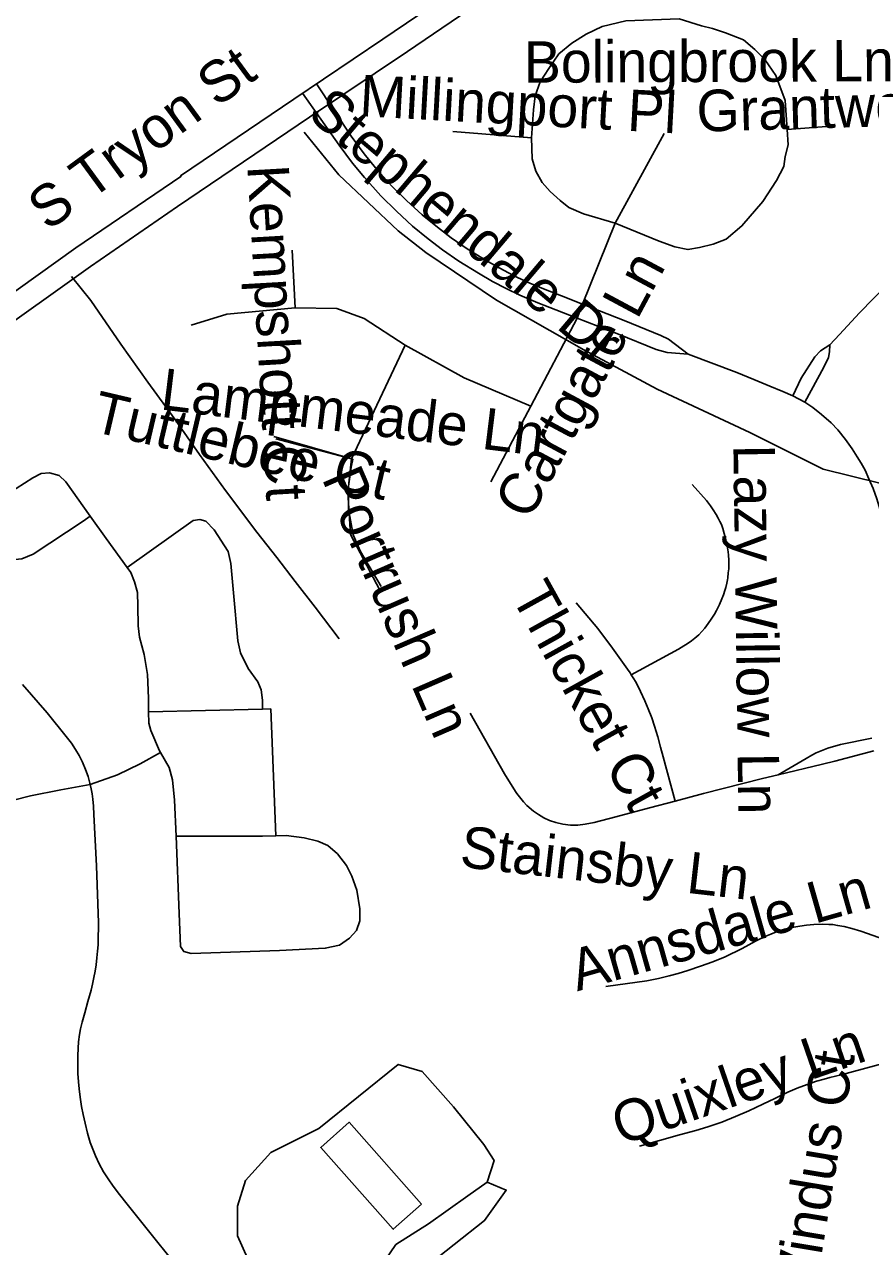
# Model space of a CAD drawing. Extents: x 1383679 to 1536984, y 460658 to 651027.
# Drawn here: x 1408734 to 1410672, y 498254 to 501053 of the extents above; entities that cross this region are included whole.
import ezdxf

# ---------------------------------------------------------------- set-up
doc = ezdxf.new("R2010")
doc.units = 0
for name, color, linetype in [('Exist Cultural Warehouse Building Footprint', 7, 'Continuous'), ('Exist Hydrographic Creek Single Shore', 7, 'Continuous'), ('Exist Road Non-System Type 51', 7, 'Continuous'), ('Exist Road Non-System Type 51 Label', 7, 'Continuous'), ('Exist Road Primary NC Label', 7, 'Continuous'), ('Exist Road Primary NC UnDivided 4 Lane Attributed', 7, 'Continuous')]:
    doc.layers.add(name, color=color, linetype=linetype)

msp = doc.modelspace()

# ---------------------------------------------------------------- linework, layer by layer
at = {"layer": 'Exist Cultural Warehouse Building Footprint'}
msp.add_lwpolyline([(1409643.3, 498351), (1409578.4, 498293.6), (1409412.5, 498481.2), (1409477.4, 498538.6), (1409643.3, 498351)], dxfattribs=at)
at = {"layer": 'Exist Hydrographic Creek Single Shore'}
msp.add_lwpolyline([(1409374.1, 500806), (1409454.2, 500708.4), (1409589.7, 500580.2), (1409652.9, 500530.4), (1409814.8, 500421.4), (1410014.7, 500307.3), (1410183, 500217.8), (1410395.1, 500118.3), (1410563.6, 500034.5), (1410693, 500002.4), (1410764.3, 499962.4), (1410867.4, 499916.8), (1411025, 499891.5), (1411092.9, 499884.4), (1411204.1, 499841.9), (1411305.7, 499821.8), (1411463.5, 499808.8), (1411647.5, 499803.5), (1411737.3, 499786.1), (1411800.7, 499760.2)], dxfattribs=at)
at = {"layer": 'Exist Road Non-System Type 51'}
for p, q in [((1409895.2, 500793.4), (1409715.2, 500807.8)), ((1410086.6, 500598), (1410198.9, 500803)), ((1410481.2, 500812.6), (1410591.7, 500820.6)), ((1410012.3, 500412), (1410086.6, 500598)), ((1409999.6, 500380.5), (1410012.3, 500412)), ((1410493.6, 500202), (1410521.4, 500187.8)), ((1409304.6, 500109.5), (1409486.1, 500057.5)), ((1409279, 499484.8), (1409018.2, 499478.7))]:
    msp.add_line(p, q, dxfattribs=at)
for points in [[(1410233.6, 501065.7), (1410111.4, 501060.9), (1410056.9, 501048), (1410020.6, 501030.4), (1409987.6, 501009.6), (1409957.9, 500985.6), (1409934.8, 500952), (1409915, 500921.5), (1409903.4, 500889.5), (1409900.1, 500857.5), (1409895.2, 500793.4)], [(1410481.2, 500812.6), (1410476.2, 500878.3), (1410454.7, 500935.9), (1410430, 500972.8), (1410406.9, 500995.2), (1410380.5, 501017.6), (1410339.2, 501033.6), (1410309.5, 501043.2), (1410284.7, 501049.6), (1410233.6, 501065.7)], [(1409403, 500917), (1409482.1, 500796.6), (1409512.2, 500756.4), (1409538.2, 500724.3), (1409574.7, 500683.6), (1409609.2, 500649.7), (1409644.9, 500616.9), (1409679.5, 500588.8), (1409711.2, 500564.3), (1409747.5, 500539.3), (1409791, 500512.2), (1409822.4, 500494.3), (1409852.1, 500478.6), (1409882.2, 500464.1), (1409922.5, 500447), (1409963.6, 500431.3), (1410012.3, 500412)], [(1409370.5, 500895.1), (1409454.7, 500776.5), (1409485.3, 500735.5), (1409512.3, 500702.2), (1409550.1, 500660.1), (1409585.8, 500625), (1409622.7, 500591.1), (1409658.4, 500562.2), (1409691.1, 500536.9), (1409728.8, 500510.8), (1409773.5, 500483), (1409806, 500464.5), (1409836.8, 500448.2), (1409868.1, 500433.1), (1409909.8, 500415.4), (1409951.3, 500399.6), (1409999.6, 500380.5)], [(1410086.6, 500598), (1410187.3, 500556.4), (1410223.6, 500543.6), (1410253.4, 500537.2), (1410279.8, 500542), (1410311.1, 500550), (1410340.8, 500561.2), (1410377.2, 500591.6), (1410425, 500647.7), (1410456.4, 500695.7), (1410472.9, 500727.7), (1410476.2, 500750.2), (1410482.8, 500777.4), (1410481.2, 500812.6)], [(1409895.2, 500793.4), (1409896.8, 500745.4), (1409905.1, 500716.5), (1409919.9, 500690.9), (1409938.1, 500670.1), (1409961.2, 500649.3), (1409981, 500633.3), (1410014, 500618.8), (1410086.6, 500598)], [(1409893.5, 500178.8), (1409741.3, 500243.5), (1409605.8, 500318.6), (1409511.9, 500379.1), (1409449.4, 500402), (1409353.5, 500404.1), (1409347.2, 500535.6)], [(1408841.6, 500475.6), (1408885.9, 500420.3), (1408954.3, 500320.5), (1409016.7, 500233.6), (1409077.9, 500148.8), (1409134.9, 500067.7), (1409194.5, 499985.4), (1409266.1, 499890.4), (1409312.1, 499831.8), (1409354.1, 499776.8), (1409399.8, 499718.4), (1409454.6, 499645.8)], [(1410578.3, 500318.8), (1410600.7, 500343.1), (1410646.3, 500392.6), (1410709.8, 500457.1), (1410733.4, 500481.8)], [(1410012.3, 500412), (1410107.1, 500374.8), (1410191.7, 500340.6), (1410208.8, 500332), (1410253.7, 500298)], [(1409353.5, 500404.1), (1409197.1, 500389.5), (1409115.8, 500364.5)], [(1409999.6, 500380.5), (1409893.5, 500178.8), (1409801.8, 500005.6)], [(1409999.6, 500380.5), (1410094.5, 500343.2), (1410181.1, 500308.2), (1410206.3, 500301.8), (1410253.7, 500298)], [(1409605.8, 500318.6), (1409482.7, 500057.8), (1409309.7, 500103.7)], [(1410253.7, 500298), (1410365.3, 500256), (1410404.5, 500239.9), (1410441.4, 500224.8), (1410470.6, 500212.4), (1410493.6, 500202)], [(1410493.6, 500202), (1410513.2, 500243.1), (1410544.1, 500291.3), (1410556.9, 500305.3), (1410578.3, 500318.8)], [(1410521.4, 500187.8), (1410564.8, 500268), (1410575.6, 500290.2), (1410577.5, 500302.7), (1410578.3, 500318.8)], [(1410521.4, 500187.8), (1410539.3, 500175.6), (1410559.8, 500159.5), (1410581.6, 500140.2), (1410596.7, 500124.3), (1410614.2, 500102.2), (1410629.5, 500081), (1410641.5, 500062.9), (1410650.3, 500048.4), (1410659.2, 500031.8), (1410668.2, 500012.2), (1410677.6, 499989.7), (1410686.3, 499966.7), (1410693.3, 499943.7), (1410697.5, 499926), (1410700.9, 499908.8), (1410703.3, 499890.7), (1410704.4, 499880.1), (1410705.7, 499857.8), (1410705.5, 499840.1), (1410704.4, 499814.2), (1410703, 499794.9)], [(1409482.7, 500057.8), (1409474.4, 499980.6), (1409480.7, 499884.6), (1409547.4, 499757.4)], [(1409486.1, 500057.5), (1409481.8, 500038.6), (1409476, 499995.2), (1409475.8, 499943), (1409486.9, 499884.2), (1409503.2, 499846.1), (1409551, 499765.3)], [(1408648.6, 499842.5), (1408654.9, 499863.9), (1408658.1, 499886), (1408653.9, 499915.6), (1408653.9, 499931.4), (1408662.2, 499949.3), (1408696, 499977.8), (1408753, 500014.7), (1408771.9, 500024.2), (1408790.9, 500026.2), (1408813.1, 500020), (1408828.9, 500005.2), (1408884.6, 499926.4)], [(1410123.7, 499563.7), (1410231.9, 499622.4), (1410243.9, 499629.4), (1410251.8, 499634.7), (1410261.4, 499641.4), (1410269, 499647.3), (1410278.2, 499655.2), (1410285.7, 499662.7), (1410292.2, 499669.9), (1410299.9, 499680.6), (1410306.9, 499690.7), (1410314.3, 499702.5), (1410318.7, 499710.6), (1410322.8, 499718.2), (1410325.7, 499724.3), (1410331.4, 499737.3), (1410334.8, 499746.4), (1410338.1, 499756.3), (1410340.3, 499763.1), (1410342.5, 499772.9), (1410344, 499781), (1410344.7, 499785.8), (1410346, 499797), (1410346.9, 499806.4), (1410347.3, 499813.6), (1410347.1, 499826.1), (1410346.4, 499837.2), (1410345.5, 499845.1), (1410344, 499854.1), (1410341.9, 499865), (1410340.5, 499872.2), (1410336.8, 499886.7), (1410333.3, 499898.5), (1410330.2, 499907.4), (1410326.8, 499914.6), (1410323, 499922.1), (1410318.2, 499930.6), (1410311.4, 499941.1), (1410304.9, 499950.5), (1410296.4, 499962.5), (1410263.3, 499999)], [(1408884.6, 499926.4), (1408867.9, 499915.6), (1408754, 499839.7), (1408727.6, 499829.1), (1408705.5, 499827), (1408668.6, 499836.5), (1408648.6, 499842.5)], [(1408884.6, 499926.4), (1408920.6, 499875.5), (1408969, 499809.2)], [(1408969, 499809.2), (1409119.9, 499916.6), (1409135.8, 499918.8), (1409149.5, 499915.6), (1409168.4, 499895.5), (1409200.1, 499846), (1409206.4, 499818.6), (1409212.8, 499751.1), (1409222.2, 499641.4), (1409228.6, 499614), (1409246.5, 499578.1), (1409268.6, 499547.5), (1409276, 499528.6), (1409279.1, 499505.3), (1409279, 499484.8)], [(1408969, 499809.2), (1408977.6, 499797.5), (1408986, 499776.3), (1408992.4, 499752.1), (1408993.4, 499720.5), (1408994.4, 499675.2), (1408997.6, 499649.8), (1409008.1, 499609.8), (1409015.5, 499564.4), (1409017.6, 499509.6), (1409018.2, 499478.7)], [(1409997.5, 499728.4), (1410047.5, 499669.4), (1410081.1, 499624.5), (1410115.4, 499576.6), (1410121, 499568), (1410123.7, 499563.7)], [(1408729.1, 499541.4), (1408785.4, 499476), (1408829.6, 499421.9), (1408841.4, 499406.5), (1408850.8, 499392.6), (1408858.9, 499378.6), (1408866.7, 499363.1), (1408873.7, 499346.2), (1408879.4, 499330.3), (1408883.8, 499315.2), (1408886.8, 499301.9), (1408888.8, 499290.7), (1408890.3, 499278.9), (1408892.1, 499262.3), (1408892.9, 499243.5), (1408898.8, 499125.8), (1408903.2, 498995.6), (1408903.4, 498981.7), (1408902.8, 498965.8), (1408902.3, 498944.8), (1408901.3, 498930.5), (1408899.9, 498915.3), (1408897.8, 498899.3), (1408895.6, 498884.9), (1408892.5, 498870), (1408889.4, 498855.1), (1408886.2, 498841.4), (1408878.8, 498815.2), (1408871.7, 498789.2), (1408865.9, 498768), (1408862.4, 498752.7), (1408860, 498739.5), (1408857.8, 498722.9), (1408856.7, 498708.3), (1408856.2, 498690.4), (1408856, 498670.1), (1408856.2, 498650.4), (1408857.3, 498631.4), (1408859.1, 498615.4), (1408861.3, 498596.4), (1408864.5, 498574.7), (1408868, 498556.6), (1408872.6, 498536.7), (1408878.3, 498513.8), (1408884.6, 498492.6), (1408890.3, 498476.8), (1408896.2, 498462), (1408904.7, 498443.8), (1408915, 498425.3), (1408925.5, 498409.1), (1408937.1, 498392.1), (1408951.1, 498373.2), (1408968.7, 498351), (1409030.1, 498274.8), (1409098.5, 498189.5)], [(1410123.7, 499563.7), (1410128.4, 499556.2), (1410134.8, 499545.4), (1410144.5, 499525.3), (1410154.7, 499504.1), (1410162.5, 499485.7), (1410170.6, 499464.9), (1410176.8, 499446.1), (1410184.6, 499421), (1410190.8, 499397.8), (1410196.7, 499375.4), (1410224, 499274.2)], [(1409309.8, 499194.9), (1409298.1, 499485.3), (1409279, 499484.8)], [(1409018.2, 499478.7), (1409018.6, 499452.7), (1409022.9, 499435.8), (1409043, 499389.3), (1409045.1, 499385.6)], [(1410224, 499274.2), (1410165.6, 499258.9), (1410088.2, 499237.9), (1410038.7, 499225), (1410018.1, 499221), (1410001.5, 499219.2), (1409984.8, 499219.3), (1409967, 499221.5), (1409950.9, 499225.3), (1409936.5, 499230), (1409923.3, 499236), (1409911.1, 499243.4), (1409900.1, 499251.1), (1409884.4, 499264.3), (1409876.6, 499272.5), (1409861.6, 499291.6), (1409858.7, 499295.8), (1409833, 499336.8), (1409754.9, 499475.3)], [(1410674.8, 499418.1), (1410603.1, 499403.6), (1410574.1, 499395.4), (1410547.2, 499384.8), (1410537.5, 499379), (1410524.6, 499371.5), (1410460.1, 499334.4)], [(1409045.1, 499385.6), (1408998.6, 499359.8), (1408947, 499334.5), (1408884.6, 499311.8)], [(1409045.1, 499385.6), (1409065.1, 499351.4), (1409072.5, 499322.9), (1409077.8, 499276.5), (1409081.1, 499194.2)], [(1410679.5, 499389.5), (1410590.4, 499365.9), (1410561.4, 499358.4), (1410460.1, 499334.4)], [(1410460.1, 499334.4), (1410424.5, 499326), (1410289, 499291.2), (1410224, 499274.2)], [(1408884.6, 499311.8), (1408816.9, 499299.8), (1408747.6, 499286.3), (1408708.5, 499276.3), (1408685.1, 499268.2)], [(1409081.1, 499194.2), (1409088.4, 499017.1), (1409091.5, 498941.2), (1409098.9, 498929.6), (1409115.8, 498925.4), (1409318.1, 498931.7), (1409422.6, 498937), (1409455.2, 498944.3), (1409478.5, 498960.2), (1409494.4, 498978.1), (1409501.6, 499000.2), (1409501.6, 499027.7), (1409495.4, 499069.8), (1409483.8, 499102.5), (1409471.1, 499126.8), (1409451.1, 499153.2), (1409428.9, 499172.2), (1409405.8, 499182.7), (1409374.1, 499190.1), (1409332.9, 499195.3), (1409309.8, 499194.9)], [(1409309.8, 499194.9), (1409279.1, 499194.2), (1409081.1, 499194.2)], [(1410703.7, 498957.5), (1410649.2, 498976.3), (1410628.8, 498982.1), (1410611.3, 498986.6), (1410596.4, 498989.5), (1410585.3, 498991.2), (1410576.1, 498991.9), (1410561.6, 498992.2), (1410541.9, 498991.2), (1410525.2, 498989.9), (1410509.5, 498988), (1410491.4, 498985), (1410474.5, 498980.9), (1410460.4, 498976.2), (1410443.3, 498969.6), (1410428.5, 498963), (1410408.4, 498953.3), (1410377.8, 498936.6), (1410338.6, 498917.6), (1410310.9, 498906.4), (1410282.1, 498895.8), (1410253.2, 498886.1), (1410231.1, 498879.7), (1410210.9, 498874.1), (1410185.9, 498868.1), (1410159.3, 498862.5), (1410065.2, 498849.2)], [(1410142.8, 498484), (1410234.5, 498509.9), (1410271.8, 498520), (1410299, 498528.1), (1410331, 498539.2), (1410362.3, 498551.6), (1410393, 498564.6), (1410424.8, 498579.7), (1410452.7, 498593.2), (1410482.5, 498607.3), (1410504, 498616.9), (1410526.4, 498625.1), (1410548.3, 498632.5), (1410565.4, 498637.7), (1410578.6, 498640.9), (1410604.3, 498647.2), (1410708.9, 498675.4)], [(1409171.9, 498132.1), (1409258, 498198.1), (1409221.4, 498278.8), (1409221.4, 498346.7), (1409239.7, 498405.4), (1409298.4, 498469.5), (1409408.3, 498524.6), (1409589.8, 498671.3), (1409644.8, 498654.8), (1409716.3, 498574.1), (1409786, 498487.9), (1409809.8, 498451.2), (1409793.3, 498401.7), (1409749.3, 498370.5), (1409659.5, 498306.3), (1409584.3, 498258.6), (1409529.3, 498177.9), (1409481.7, 498143.1), (1409399.2, 498124.7), (1409335, 498143.1), (1409258, 498198.1)], [(1409793.3, 498401.7), (1409837.3, 498383.3), (1409787.8, 498313.6), (1409648.5, 498203.6), (1409529.3, 498177.9)]]:
    msp.add_lwpolyline(points, dxfattribs=at)
at = {"layer": 'Exist Road Primary NC UnDivided 4 Lane Attributed'}
for points in [[(1408282.2, 500133.7), (1408851.4, 500541), (1409092.2, 500704.4), (1409091.4, 500706), (1409350.8, 500881.8), (1409554.4, 501019), (1409955.2, 501290.9), (1410378.7, 501574.4), (1410570, 501703), (1410673, 501756.5), (1410740.3, 501789.8), (1410820.8, 501823.9), (1411000.5, 501885.1), (1411529.8, 502054.9), (1411847.2, 502157), (1412098.9, 502238.4), (1412527.8, 502378.6), (1412640.1, 502416.6), (1412816.7, 502485.5)], [(1408403.8, 500155.9), (1408884.7, 500498.3), (1409084.4, 500636.2), (1409386.4, 500840.8), (1409611, 500991.1), (1409990, 501249.1), (1410400.4, 501525.6), (1410584.7, 501648), (1410691.5, 501708.5), (1410754.3, 501737.1), (1410834, 501772), (1411036.9, 501840.9), (1411523.5, 501997.4), (1411550.5, 502007.4), (1412095.8, 502181.8), (1412152.3, 502198.1), (1412546.4, 502328.2), (1412648.6, 502363.1), (1412824.4, 502429.7), (1412995.1, 502497.1)]]:
    msp.add_lwpolyline(points, dxfattribs=at)

# ---------------------------------------------------------------- texts
at = {"layer": 'Exist Road Non-System Type 51 Label'}
for s, rotation, p in [('Bolingbrook Ln', 0.2504, (1409877.9, 500919.1)), ('Millingport Pl', 356.8581, (1409499.6, 500843.1)), ('Grantwood Pl', 1.6374, (1410274.5, 500807.1)), ('Stephendale Dr', 319.6948, (1409378.2, 500843.5)), ('Kempshott Ct', 273.2814, (1409244.2, 500728.8)), ('Cartgate Ln', 61.8084, (1409890.4, 499914.2)), ('Lampmeade Ln', 353.0042, (1409042.8, 500171.5)), ('Tuttlebee Ct', 346.7384, (1408884.3, 500122)), ('Lazy Willow Ln', 270.7847, (1410357.6, 500090.2)), ('Portrush Ln', 293.4402, (1409413.9, 500013.6)), ('Thicket Ct', 298.9846, (1409846.6, 499744.5)), ('Stainsby Ln', 353.4624, (1409728.7, 499123.9)), ('Annsdale Ln', 15.8704, (1410000, 498838.2)), ('Quixley Ln', 19.0539, (1410100, 498484.8)), ('Windus Ct', 80.5373, (1410539.7, 498114.6))]:
    msp.add_text(s, height=95, rotation=rotation, dxfattribs=at).set_placement(p)
at = {"layer": 'Exist Road Primary NC Label'}
msp.add_text('S Tryon St', height=95, rotation=36.1761, dxfattribs=at).set_placement((1408787.3, 500578))

doc.saveas('drawing.dxf')
